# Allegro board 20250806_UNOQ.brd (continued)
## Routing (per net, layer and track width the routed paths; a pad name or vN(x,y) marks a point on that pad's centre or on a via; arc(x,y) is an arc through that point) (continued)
MCU_TRACE_D0: length 69.3
  S6 w0.064: v4(14,4.59) 13.26,4.59 12.41,5.44 9.47,5.44 9.2,5.71 6.23,5.71 4.96,6.98 4.96,14.77 4.22,15.51 4.22,20.24 v4(4.67,20.7)
  G7 w0.064: v4(14,4.59) 14.16,4.75 18.8,4.75 20.13,6.08 20.13,9.33 v5(20.37,9.57) ; v4(4.67,20.7) 5.08,20.7 5.21,20.57 6.5,20.57 7.06,20.02 8,20.02 8.26,20.27 9.96,20.27 10.59,20.9 12.47,20.9 13.15,21.58 v5(13.15,21.86)
  BOTTOM w0.051: MCU1.D3 13.16,22.37 13.16,21.86
  BOTTOM w0.066: JMISC1.6 42.54,10.42 41.58,9.46 20.48,9.46 v5(20.37,9.57) ; 13.16,21.86 v5(13.15,21.86)
MCU_TRACE_D2: length 42.4
  S6 w0.064: v4(12.7,22.38) 12.7,17.47 11.71,16.48 11.71,15.32 17.57,9.46 v5(17.57,9.31)
  G7 w0.064: v4(12.7,22.38) 13.13,22.38 13.31,22.2 v5(13.39,22.2)
  BOTTOM w0.066: v5(17.57,9.31) 17.76,9.5 19.97,9.5 20.29,9.82 21.85,9.82 21.99,9.68 40.28,9.68 41.27,10.67 JMISC1.8
MCU_TRACE_D3: length 66.5
  S6 w0.064: v4(4.88,21.64) 4.95,21.56 4.95,20.5 4.37,19.91 4.37,15.58 5.1,14.85 5.1,7.04 6.29,5.85 9.26,5.85 9.49,5.62 12.45,5.62 13.23,4.84 v4(13.87,4.84)
  G7 w0.064: v4(13.87,4.84) 14,4.97 18.51,4.97 19.56,6.02 19.56,7.96 19.92,8.32 19.92,9.85 v5(19.98,9.91) ; v5(12.9,23.11) 12.69,23.32 12.35,23.32 12.14,23.11 12.14,22.02 11.66,21.54 11.02,21.54 10.9,21.41 8.56,21.41 8.1,20.95 5.36,20.95 4.88,21.44 v4(4.88,21.64)
  BOTTOM w0.066: 40,11.98 40,11.29 38.69,9.98 20.05,9.98 v5(19.98,9.91)
MCU_USART1_RX: length 14.2
  S6 w0.064: v4(4.34,20.7) 4.62,20.98 4.62,23.24 4.57,23.29 v4(4.57,23.34)
  G7 w0.064: v4(4.57,23.34) 4.72,23.5 7.68,23.5 7.94,23.75 9.5,23.75 9.83,24.08 10.82,24.08 11.13,23.77 12.24,23.77 v5(12.4,23.61) ; v5(7.01,19.74) 6.99,19.74 6.3,20.42 4.62,20.42 v4(4.34,20.7)
MCU_USART1_RX_CONN: length 66.5
  S3 w0.064: v3(16.84,1.4) 16.84,1.3 17.22,0.92 21.24,0.92 24.02,3.7 24.02,5.76 24.46,6.2 31.27,6.2 32.56,4.9 48.15,4.9 49.6,6.35 50.6,6.35 50.8,6.15 JDIGITAL1.1
  S6 w0.064: v3(16.84,1.4) 17.3,1.85 17.3,2.79 11.44,8.65 8.9,8.65 6.76,10.79 6.76,12.88 6.92,13.05 6.92,17.38 8.64,19.09 v4(8.64,19.46)
  G7 w0.064: v4(8.64,19.46) 7.62,19.46 v5(7.39,19.23)
  BOTTOM w0.064: R2624.2 v5(7.39,19.23)
MCU_USART1_TX: length 3.5
  BOTTOM w0.051: 15.44,23.37 14.64,23.37 MCU1.B5
  BOTTOM w0.064: 15.44,23.37 15.8,23.01 15.8,22.81 16.13,22.48 R2623.1
MCU_USART1_TX_CONN: length 62.7
  S3 w0.064: JDIGITAL1.2 49.78,6.6 49.55,6.6 48.03,5.08 32.64,5.08 31.34,6.38 24.39,6.38 23.84,5.83 23.84,3.78 21.16,1.1 17.86,1.1 17.64,1.32 v3(17.37,1.32)
  S6 w0.064: v3(17.37,1.32) 18.01,1.32 18.54,1.85 18.54,5.43 18.29,5.68 18.29,6.9 19.14,7.75 v4(19.14,8.92)
  G7 w0.064: v4(19.14,8.92) 19.14,10.51 18.83,10.82 18.83,12.78 18.49,13.12 18.49,13.79 19.53,14.83 v5(19.53,15.16)
  BOTTOM w0.064: R2623.2 18.31,22.48 19.3,21.49 19.3,15.49 19.53,15.27 v5(19.53,15.16)
MCU_VCAP: length 37
  V5 w0.203: v3(7.35,26.69) 8.2,25.84 8.2,19.56 7.39,18.75 v3(7.09,18.75)
  S6 w0.203: v3(7.35,26.69) 7.37,26.69 7.37,26.7 7.39,26.72 v5(7.62,26.72)
  S6 w0.254: v3(7.09,18.75) 7.1,18.76 v4(7.37,18.76)
  G7 w0.203: v5(19.25,14.99) 19.25,15.01 18.87,15.39 8.1,15.39 7.37,16.12 v4(7.37,18.76)
  BOTTOM w0.051: 8.11,26.61 MCU1.N11
  BOTTOM w0.2: MCU1.A4 15.11,23.11 16.15,22.07 C2501.1 16.31,21.84 16.51,21.64 18.14,21.64 18.92,20.85 18.92,15.37 19.23,15.07 19.23,14.99 v5(19.25,14.99)
  BOTTOM w0.203: v5(7.62,26.72) 8,26.72 8.11,26.61
MCU_VREF+: length 91.1
  V5 w0.524: v3(11.74,51.6) 10.71,52.63 7.93,52.63 7.11,51.81 7.11,50.61 4.8,48.3 4.8,32.79 7.7,29.89 7.7,27.96 6.46,26.72 6.44,26.72 5.58,25.86 5.58,22.23 7.14,20.68 v3(7.57,20.68)
  S6 w0.203: v4(7.87,20.68) v3(7.57,20.68)
  S6 w0.254: v3(11.74,51.6) v5(12.04,51.6)
  G7 w0.203: v4(7.87,20.68) 7.95,20.6 v5(8.48,20.6)
  BOTTOM w0.2: v5(8.48,20.6) C2521.1 C2520.1 9.04,20.76 MCU1.L1
  BOTTOM w0.254: v5(12.04,51.6) 12.4,51.24 14.39,51.24 18.5,47.13 18.5,43.3 20.22,41.58 34.14,41.58 34.98,42.42 40.57,42.42 41.26,43.11 U2501.3 44.06,43.63 44.39,43.96 C2614.1 46.6,44.37 48.11,44.37 48.44,44.7 JDIGITAL1.16
MCU_VREF_EN: length 133.3
  TOP w0.066: v2(0.93,19.9) 1.04,19.79 1.04,4.45 1.78,3.71 3.62,3.71 v6(4.16,4.25)
  S3 w0.064: v2(0.93,19.9) v3(1.93,19.9)
  S6 w0.064: v4(3.4,19.65) 3.15,19.9 v3(1.93,19.9)
  G7 w0.064: v5(48.98,3.82) 47.45,5.35 42.13,5.35 40.39,7.09 24.06,7.09 22.89,5.92 22.89,3.51 21.05,1.67 12.71,1.67 8.96,5.42 5.61,5.42 4.45,4.25 v6(4.16,4.25) ; v4(3.4,19.65) 3.61,19.86 5.9,19.86 v5(6.11,19.65)
  BOTTOM w0.058: 9.03,21.87 8.64,21.87 8.42,21.65 8.42,21.33 8.04,20.95 6.51,20.95 5.87,20.31 5.87,19.89 v5(6.11,19.65)
  BOTTOM w0.066: U2501.6 45.37,44.92 R2515.1 47.56,44.92 48.53,45.89 51.64,45.89 52.02,45.51 52.02,4.45 51.39,3.82 v5(48.98,3.82) ; 9.03,21.87 9.27,22.11 MCU1.M2
MIC2_BIAS: length 47.5
  S3 w0.127: v2(43.85,17.59) 43.6,17.35 42.5,17.35 42.41,17.44 40.71,17.44 v2(40.39,17.11)
  S3 w0.15: v2(43.85,17.59) 44.08,17.83 47.01,17.83 48.13,16.71 48.13,9.98 47.39,9.24 47.38,9.24 47.22,9.08 47.22,9.07 45.85,7.7 23.7,7.7 22.49,6.49 22.49,4.26 22.27,4.03 20.89,4.03 20.66,4.26 v3(20.66,4.35)
  S6 w0.15: v3(20.66,4.35) 20.62,4.31 v5(19.94,4.31)
MIC2_BIAS_CONN: length 6.5
  BOTTOM w0.15: JMISC1.33 24.76,7.55 23.19,5.98 22.14,5.98 21.6,5.44 21.04,5.44 20.61,5.01 D26067.2 20.61,4.88 20.61,4.48 R2646.1
MIC2_INN: length 46.1
  S3 w0.127: v2(43.82,17.06) 43.6,16.84 42.7,16.84 42.62,16.76 42.21,16.76 41.72,17.26 41.1,17.26 v2(39.82,15.98)
  S3 w0.15: v2(43.82,17.06) 44.13,17.37 46.83,17.37 47.83,16.37 47.83,10.24 45.62,8.03 23.67,8.03 22.24,6.59 22.24,4.49 22.07,4.32 21.44,4.32 v3(21.35,4.41)
  S6 w0.15: v5(21.02,4.37) 21.31,4.37 v3(21.35,4.41)
MIC2_INN_CONN: length 6.7
  BOTTOM w0.15: R2637.1 21.5,4.39 D26066.2 22.31,5.72 23.3,5.72 24.62,7.04 25.56,7.04 26.05,7.53 26.05,8.07 JMISC1.31
MIC2_INP: length 44.9
  S3 w0.127: v2(39.54,15.7) 40.16,15.7 40.46,16 40.92,16 41.25,16.33 42.48,16.33 42.58,16.23 43.52,16.23 v2(43.82,16.53)
  S3 w0.15: v3(21.87,4.66) 21.95,4.74 21.95,6.64 23.67,8.36 45.42,8.36 47.57,10.52 47.57,16.27 46.76,17.08 44.37,17.08 v2(43.82,16.53)
  S6 w0.15: v5(22.58,4.37) 22.16,4.37 v3(21.87,4.66)
MIC2_INP_CONN: length 7.5
  BOTTOM w0.15: JMISC1.29 27.32,8.07 27.32,7.64 26.41,6.73 24.71,6.73 23.42,5.44 22.39,5.44 22.09,5.14 D26065.2 22.09,4.38 R2636.1
MIPI_DSI0_CLK_M: length 68.9
  TOP w0.058: v2(38.73,50.37) 38.54,50.57 38.3,50.57 38.06,50.81 38.06,51 37.76,51.3 37.53,51.3 U3001.H8
  S3 w0.051: v2(30.17,29.68) 29.97,29.49 29.97,28.85 29.59,28.48 29.59,28.35 29.6,28.35 29.6,28.33
  S3 w0.053: 29.6,28.33 29.6,28.14 27.01,25.55 23.25,25.55 21.79,24.09 19.29,24.09 19.16,24.22 18.94,24.22 v3(18.77,24.05) ; v2(38.73,50.37) 38.93,50.56 39.05,50.56 39.25,50.36 39.25,48.85 39.38,48.72 39.38,48.29 v3(39.2,48.11)
  S6 w0.053: v3(18.77,24.05) 18.58,24.24 18.32,24.24 18.14,24.42 18.14,28.1 18.26,28.22 18.57,28.22 18.62,28.27 18.62,28.47 18.57,28.53 18.26,28.53 18.14,28.65 18.14,28.95 18.26,29.07 18.57,29.07 18.62,29.12 18.62,29.32 18.57,29.38 18.26,29.38 18.14,29.5 18.14,29.8 18.26,29.92 19.1,29.92 19.15,29.97 19.15,30.17 19.1,30.22 18.26,30.22 18.14,30.35 18.14,30.64 18.26,30.76 19.1,30.76 19.15,30.82 19.15,31.02 19.1,31.07 18.26,31.07 18.14,31.19 18.14,31.56 18.26,31.68 19.11,31.68 19.16,31.73 19.16,31.93 19.11,31.99 18.26,31.99 18.14,32.11 18.14,40.1 19.5,41.47 33.17,41.47 34.34,42.64 36.27,42.64 39.38,45.74 39.38,47.93 v3(39.2,48.11)
MIPI_DSI0_CLK_M_CONN: length 22
  TOP w0.058: v2(42.22,51.59) 42.13,51.5 42.13,51.13 41.98,50.98 41.45,50.98 41.32,51.12 41.32,51.53 41.26,51.59 41.14,51.59 41.08,51.53 41.08,51.12 40.94,50.98 40.61,50.98 40.2,50.57 39.44,50.57 39.24,50.37
  S3 w0.053: v3(42.99,53.57) 43.18,53.76 43.18,54.04 43.38,54.24 44.18,54.24 44.5,53.92 44.5,52.61 44.18,52.29 43.53,52.29 43.48,52.24 43.48,52.05 43.36,51.93 43.15,51.93 43.03,52.05 43.03,52.24 42.98,52.29 42.29,52.29 42.11,52.11 42.11,51.7 v2(42.22,51.59)
  S6 w0.053: v3(42.99,53.57) 43.04,53.52 v5(43.04,53.29)
  BOTTOM w0.058: v5(43.04,53.29) 43.14,53.19 43.14,52.91 43.08,52.85 43.07,52.85 43.01,52.79 43.01,52.67 43.07,52.61 43.08,52.61 43.14,52.56 43.14,52.3 43.3,52.15 44.04,52.15 44.16,52.03 44.16,51.59 43.96,51.39 42.18,51.39 42.12,51.45 42.12,51.73 42.3,51.91 U2612.1 U2612.10 42.3,53.24 42.12,53.42 42.12,53.57 42.32,53.77 43.02,53.77 43.25,54 43.25,54.89 43.31,54.95 JMEDIA1.3
MIPI_DSI0_CLK_P: length 68.9
  TOP w0.058: v2(38.73,50.91) 38.54,50.71 38.35,50.71 38.19,50.87 38.19,51.06 37.82,51.43 37.49,51.43 U3001.G8
  S3 w0.051: v2(29.77,29.28) 29.79,29.28 29.86,29.21 29.86,28.9 29.48,28.52 29.48,28.35 29.48,28.35 29.48,28.33
  S3 w0.053: 29.48,28.33 29.48,28.18 26.96,25.67 23.2,25.67 21.74,24.21 20.87,24.21 20.81,24.26 20.81,24.32 20.76,24.37 20.65,24.37 20.6,24.32 20.6,24.26 20.55,24.21 20.44,24.21 20.39,24.26 20.39,24.32 20.33,24.37 20.23,24.37 20.18,24.32 20.18,24.26 20.12,24.21 20.02,24.21 19.96,24.26 19.96,24.32 19.91,24.37 19.8,24.37 19.75,24.32 19.75,24.26 19.7,24.21 19.34,24.21 19.21,24.34 18.96,24.34 v3(18.77,24.53) ; v2(38.73,50.91) 38.73,50.9 38.95,50.68 39.1,50.68 39.37,50.41 39.37,48.9 39.5,48.77 39.5,48.29 v3(39.68,48.11)
  S6 w0.053: v3(39.68,48.11) 39.5,47.93 39.5,45.69 36.32,42.52 34.39,42.52 33.22,41.35 19.55,41.35 18.25,40.05 18.25,32.16 18.31,32.1 19.16,32.1 19.28,31.98 19.28,31.68 19.16,31.56 18.31,31.56 18.25,31.51 18.25,31.24 18.31,31.19 19.15,31.19 19.27,31.07 19.27,30.77 19.15,30.65 18.31,30.65 18.25,30.59 18.25,30.39 18.31,30.34 19.15,30.34 19.27,30.22 19.27,29.92 19.15,29.8 18.31,29.8 18.25,29.75 18.25,29.55 18.31,29.49 18.62,29.49 18.74,29.37 18.74,29.07 18.62,28.95 18.31,28.95 18.25,28.9 18.25,28.7 18.31,28.64 18.62,28.64 18.74,28.52 18.74,28.23 18.62,28.1 18.31,28.1 18.25,28.05 18.25,24.47 18.37,24.36 18.6,24.36 v3(18.77,24.53)
MIPI_DSI0_CLK_P_CONN: length 22
  TOP w0.058: 39.24,50.91 39.24,50.83 39.36,50.71 39.57,50.71 39.63,50.77 39.63,50.82 39.69,50.88 39.8,50.88 39.86,50.82 39.86,50.77 39.92,50.71 40.15,50.71 40.55,51.11 40.89,51.11 40.95,51.17 40.95,51.58 41.08,51.72 41.31,51.72 41.45,51.58 41.45,51.17 41.51,51.11 41.92,51.11 42,51.19 42,51.48 v2(41.89,51.59)
  S3 w0.053: v2(41.89,51.59) 42,51.7 42,52.16 42.25,52.41 43.03,52.41 43.15,52.29 43.15,52.1 43.2,52.05 43.31,52.05 43.36,52.1 43.36,52.29 43.48,52.41 44.13,52.41 44.38,52.66 44.38,53.87 44.13,54.12 43.43,54.12 43.3,53.99 43.3,53.74 v3(43.47,53.57)
  S6 w0.053: v3(43.47,53.57) 43.37,53.47 v5(43.37,53.29)
  BOTTOM w0.058: v5(43.37,53.29) 43.27,53.19 43.27,52.36 43.35,52.28 44.1,52.28 44.29,52.09 44.29,51.53 44.02,51.26 42.12,51.26 41.98,51.39 41.98,51.73 41.8,51.91 U2612.2 U2612.9 41.8,53.23 41.99,53.42 41.99,53.63 42.26,53.9 42.96,53.9 43.11,54.05 43.11,54.89 43.05,54.95 JMEDIA1.5
MIPI_DSI0_L0_M: length 68.9
  TOP w0.058: v2(38.71,51.69) 38.49,51.91 38.07,51.91 37.9,52.08 37.51,52.08 U3001.F8 ; 30.17,28.48 v2(30.12,28.35)
  S3 w0.053: v2(30.12,28.35) 30.04,28.35 30.02,28.33 30.02,28.03 27.24,25.25 23.5,25.25 21.39,23.14 19.53,23.14 v3(19.33,22.94) ; v2(38.71,51.69) 38.9,51.88 39.15,51.88 40.12,50.91 40.12,49.86 v3(39.94,49.68)
  S6 w0.053: v3(39.94,49.68) 40.12,49.5 40.12,49.25 40.66,48.71 40.66,47.06 40.59,46.98 40.33,46.98 40.28,47.04 40.28,48.32 39.89,48.71 38.94,48.71 38.69,48.46 38.69,45.74 36.1,43.14 34.19,43.14 32.95,41.9 19.26,41.9 17.63,40.27 17.63,24.32 18.84,23.11 19.15,23.11 v3(19.33,22.94)
MIPI_DSI0_L0_M_CONN: length 22
  TOP w0.058: R1503.2 39.42,51.89 39.75,51.89 39.99,51.65 40.23,51.65 40.34,51.54 v2(40.35,51.54)
  S3 w0.053: v2(40.35,51.54) 40.47,51.66 40.89,51.66 41.41,51.14 41.41,50.58 41.32,50.49 41.11,50.49 v3(40.92,50.68)
  S6 w0.053: v3(40.92,50.68) 40.85,50.61 v5(40.65,50.61) ; v5(42.3,50.7) 42.49,50.51 42.86,50.51 43.19,50.84 43.19,51.34 43.14,51.39 43.05,51.39 42.99,51.44 42.99,51.55 43.05,51.6 43.14,51.6 43.19,51.66 43.19,51.76 43.14,51.82 43.05,51.82 42.99,51.87 42.99,51.98 43.05,52.03 43.14,52.03 43.19,52.08 43.19,52.39 44.24,53.44 44.24,55.53 44.11,55.66 43.69,55.66 43.64,55.61 43.64,55.4 43.52,55.28 43.32,55.28 43.19,55.4 43.19,55.61 43.14,55.66 43.03,55.66 42.98,55.61 42.98,55.4 42.86,55.28 42.66,55.28 42.53,55.4 42.53,55.61 42.48,55.66 41.76,55.66 41.6,55.82 41.6,56.07 v5(41.48,56.19)
  BOTTOM w0.058: v5(41.48,56.19) 41.59,56.29 41.59,56.77 41.19,57.17 39.79,57.17 39.3,57.66 39.3,58.79 39.24,58.85 JMEDIA1.12 ; v5(42.3,50.7) U2611.10 41.16,50.7 40.98,50.52 40.74,50.52 v5(40.65,50.61)
MIPI_DSI0_L0_P: length 68.8
  TOP w0.058: SOC1.R30 v2(29.82,28.35) ; v2(38.71,52.22) 38.53,52.04 38.13,52.04 37.96,52.21 37.51,52.21 U3001.E8
  S3 w0.053: v2(29.82,28.35) 29.89,28.35 29.91,28.33 29.91,28.08 27.2,25.37 23.45,25.37 21.34,23.26 20.08,23.26 20.03,23.31 20.03,23.37 19.97,23.42 19.87,23.42 19.81,23.37 19.81,23.31 19.76,23.26 19.49,23.26 v3(19.33,23.41) ; v3(40.41,49.68) 40.23,49.86 40.23,50.95 39.19,51.99 38.94,51.99 v2(38.71,52.22)
  S6 w0.053: v3(40.41,49.68) 40.23,49.5 40.23,49.3 40.78,48.76 40.78,47.01 40.64,46.87 40.28,46.87 40.16,46.99 40.16,48.27 39.84,48.59 38.99,48.59 38.81,48.41 38.81,45.69 36.14,43.03 34.24,43.03 32.99,41.78 19.3,41.78 17.74,40.22 17.74,24.37 18.88,23.23 19.15,23.23 v3(19.33,23.41)
MIPI_DSI0_L0_P_CONN: length 22
  TOP w0.058: v2(40.35,51.87) 40.26,51.78 40.05,51.78 39.81,52.02 39.42,52.02 R1504.2
  S3 w0.053: v2(40.35,51.87) 40.44,51.78 40.94,51.78 41.53,51.19 41.53,50.53 41.37,50.37 41.09,50.37 v3(40.92,50.2)
  S6 w0.053: v3(40.92,50.2) 40.84,50.28 v5(40.65,50.28) ; v5(42.3,50.2) 42.49,50.39 42.91,50.39 43.31,50.79 43.31,52.34 44.36,53.39 44.36,55.58 44.16,55.78 43.65,55.78 43.52,55.66 43.52,55.45 43.47,55.4 43.36,55.4 43.31,55.45 43.31,55.66 43.19,55.78 42.99,55.78 42.86,55.66 42.86,55.45 42.81,55.4 42.7,55.4 42.65,55.45 42.65,55.66 42.53,55.78 41.81,55.78 41.72,55.87 41.72,56.09 v5(41.81,56.19)
  BOTTOM w0.058: v5(40.65,50.28) 40.75,50.38 40.98,50.38 41.16,50.2 U2611.9 v5(42.3,50.2) ; JMEDIA1.10 39.5,58.85 39.44,58.79 39.44,57.71 39.85,57.3 41.25,57.3 41.72,56.83 41.72,56.27 v5(41.81,56.19)
MIPI_DSI0_L1_M: length 68.8
  TOP w0.058: U3001.H6 36.71,51.01 36.71,50.63 37.1,50.24 37.1,49.88 v2(36.91,49.68)
  S3 w0.05: v2(31.04,28.47) 31.16,28.35 31.16,28.33
  S3 w0.053: 31.16,28.33 31.16,27.8 27.77,24.42 24.47,24.42 20.75,20.7 20.68,20.7 20.67,20.71 20.59,20.71 20.52,20.64 20.52,20.56 20.53,20.55 20.53,20.47 20.45,20.4 20.37,20.4 20.36,20.41 20.29,20.41 20.21,20.33 20.21,20.26 20.22,20.25 20.22,20.17 20.09,20.04 19.74,20.04 19.69,20.09 19.69,20.15 19.63,20.2 19.53,20.2 19.47,20.15 19.47,20.09 19.42,20.04 19.2,20.04 v3(19.02,20.21) ; v2(36.91,49.68) 36.91,49.46 v3(36.96,49.4)
  S6 w0.053: v3(36.96,49.4) 37.12,49.56 37.12,49.79 37.26,49.93 37.83,49.93 38.07,49.69 38.07,49.06 37.03,48.02 37.03,45.26 35.76,43.99 33.98,43.99 32.55,42.56 18.98,42.56 16.86,40.43 16.86,24.21 18.47,22.6 18.47,20.2 18.65,20.02 18.83,20.02 v3(19.02,20.21)
MIPI_DSI0_L1_M_CONN: length 22.3
  TOP w0.058: v2(40.12,48.52) 40.23,48.62 40.23,48.82 40.09,48.96 39.48,48.96 38.8,48.28 37.32,48.28 37.11,48.49 37.11,48.98 R1505.2
  S3 w0.053: v2(40.12,48.52) 40.23,48.63 40.23,48.83 40.41,49.01 41.19,49.01 v3(41.36,49.18)
  S6 w0.053: v3(41.36,49.18) 41.62,49.18 v5(41.64,49.2)
  BOTTOM w0.058: JMEDIA1.6 43.05,58.85 43.11,58.79 43.11,57.85 43.37,57.59 44.99,57.59 46.24,56.34 46.24,53.26 44.86,51.88 44.86,50.75 43.13,49.02 42.71,49.02 42.53,49.2 U2611.4 v5(41.64,49.2) U2611.7
MIPI_DSI0_L1_P: length 68.8
  TOP w0.058: v2(37.44,49.68) 37.24,49.89 37.24,50.29 36.84,50.69 36.84,51.01 U3001.H7
  S3 w0.05: 31.27,28.33 31.27,28.35 31.27,28.35 31.27,28.64 31.16,28.74 31.16,28.75 v2(31.04,28.87)
  S3 w0.053: v3(37.44,49.4) v2(37.44,49.68) ; 31.27,28.33 31.27,27.75 27.82,24.3 24.52,24.3 20.14,19.92 19.21,19.92 v3(19.02,19.74)
  S6 w0.053: v3(37.44,49.4) 37.23,49.61 37.23,49.74 37.31,49.81 37.78,49.81 37.96,49.64 37.96,49.11 36.92,48.07 36.92,45.31 35.71,44.11 33.93,44.11 32.5,42.67 18.93,42.67 16.74,40.48 16.74,24.16 18.35,22.55 18.35,20.15 18.6,19.9 18.81,19.9 18.97,19.74 v3(19.02,19.74)
MIPI_DSI0_L1_P_CONN: length 22.3
  TOP w0.058: v2(40.45,48.52) 40.36,48.61 40.36,48.88 40.15,49.09 39.42,49.09 38.74,48.41 37.38,48.41 37.24,48.55 37.24,48.98 R1506.2
  S3 w0.053: v3(41.36,48.7) 41.17,48.89 40.46,48.89 40.34,48.78 40.34,48.63 v2(40.45,48.52)
  S6 w0.053: v3(41.36,48.7) v5(41.64,48.7)
  BOTTOM w0.058: JMEDIA1.4 43.31,58.85 43.25,58.79 43.25,57.9 43.43,57.72 45.05,57.72 46.37,56.4 46.37,53.2 44.99,51.82 44.99,50.69 43.18,48.88 42.72,48.88 42.54,48.7 U2611.5 v5(41.64,48.7) U2611.6
MIPI_DSI0_L2_M: length 68.9
  TOP w0.058: v2(38.71,52.93) 38.51,53.13 38.33,53.13 38.07,52.88 37.51,52.88 U3001.D8
  S3 w0.053: v3(39.01,52.96) 38.74,52.96 v2(38.71,52.93) ; v3(19.22,21.66) 19.41,21.84 20.4,21.84 20.93,22.37 21.2,22.37 23.78,24.95 27.48,24.95 30.43,27.9 30.43,28.74 v2(30.57,28.88)
  S6 w0.053: v3(19.22,21.66) 18.98,21.9 18.8,21.9 18.68,22.03 18.68,22.79 17.18,24.29 17.18,40.4 19.09,42.31 32.65,42.31 33.98,43.64 36,43.64 38.21,45.84 38.21,48.59 38.5,48.88 38.5,50.28 39.22,51 39.4,51 39.52,50.87 39.6,50.87 39.67,50.95 39.67,51.02 39.55,51.15 39.55,51.32 39.8,51.58 39.8,52.9 39.55,53.15 39.2,53.15 v3(39.01,52.96)
MIPI_DSI0_L2_M_CONN: length 22.3
  TOP w0.058: R1507.2 39.4,53.12 39.5,53.12 v2(39.6,53.02)
  S3 w0.053: v3(41.41,54.63) 41.24,54.8 40.99,54.8 40.74,55.05 40.74,56.85 40.63,56.96 40.26,56.96 40.14,56.84 40.14,56.11 40.02,55.99 39.01,55.99 38.96,55.94 38.96,55.83 39.01,55.78 40.02,55.78 40.14,55.65 40.14,55.45 40.02,55.33 39.01,55.33 38.96,55.28 38.96,55.17 39.01,55.12 40.02,55.12 40.14,54.99 40.14,53.86 40.19,53.81 40.24,53.81 40.29,53.76 40.29,53.65 40.24,53.6 40.19,53.6 40.14,53.55 40.14,53.27 40,53.13 39.71,53.13 v2(39.6,53.02)
  S6 w0.053: v5(40.71,52.05) 40.6,52.16 40.6,52.39 40.53,52.46 40.53,53.35 40.58,53.4 41.29,53.4 41.41,53.52 41.41,53.72 41.29,53.85 40.58,53.85 40.53,53.9 40.53,54.68 40.66,54.81 41.23,54.81 v3(41.41,54.63)
  BOTTOM w0.058: JMEDIA1.9 39.5,54.95 39.44,54.89 39.44,54.04 39.68,53.8 40.42,53.8 40.62,53.6 40.62,53.2 U2612.7 U2612.4 v5(40.71,52.05)
MIPI_DSI0_L2_P: length 68.9
  TOP w0.058: U3001.C8 37.51,53.01 38.02,53.01 38.27,53.26 38.53,53.26 v2(38.71,53.44)
  S3 w0.053: v3(19.22,22.14) 19.4,21.96 19.7,21.96 19.76,22.01 19.76,22.11 19.81,22.16 19.92,22.16 19.97,22.11 19.97,22.01 20.02,21.96 20.35,21.96 20.88,22.49 21.16,22.49 23.73,25.07 27.43,25.07 30.31,27.95 30.31,28.74 v2(30.17,28.88) ; v3(39.01,53.44) v2(38.71,53.44)
  S6 w0.053: v3(39.01,53.44) 39.19,53.26 39.6,53.26 39.92,52.95 39.92,51.53 39.66,51.27 39.66,51.2 39.79,51.07 39.79,50.9 39.65,50.76 39.47,50.76 39.35,50.88 39.27,50.88 38.62,50.23 38.62,48.83 38.33,48.54 38.33,45.8 36.05,43.52 34.03,43.52 32.7,42.19 19.13,42.19 17.3,40.35 17.3,24.34 18.8,22.84 18.8,22.07 18.85,22.02 19.11,22.02 v3(19.22,22.14)
MIPI_DSI0_L2_P_CONN: length 22.3
  TOP w0.058: v2(39.6,53.35) 39.5,53.25 39.4,53.25 R1508.2
  S3 w0.053: v3(41.41,55.11) 41.22,54.92 41.04,54.92 40.86,55.1 40.86,56.9 40.68,57.08 40.21,57.08 40.02,56.89 40.02,56.16 39.97,56.11 38.96,56.11 38.84,55.98 38.84,55.78 38.96,55.66 39.97,55.66 40.02,55.61 40.02,55.5 39.97,55.45 38.96,55.45 38.84,55.32 38.84,55.12 38.96,55 39.97,55 40.02,54.95 40.02,53.32 39.95,53.24 39.71,53.24 v2(39.6,53.35)
  S6 w0.053: v5(40.38,52.05) 40.48,52.15 40.48,52.34 40.41,52.41 40.41,53.39 40.53,53.52 41.24,53.52 41.3,53.57 41.3,53.68 41.24,53.73 40.53,53.73 40.41,53.85 40.41,54.73 40.61,54.93 41.23,54.93 v3(41.41,55.11)
  BOTTOM w0.058: JMEDIA1.11 39.24,54.95 39.3,54.89 39.3,53.99 39.62,53.67 40.36,53.67 40.49,53.54 40.49,53.2 U2612.6 U2612.5 40.3,52.13 v5(40.38,52.05)
MIPI_DSI0_L3_M: length 68.9
  TOP w0.058: v2(35.71,49.68) 35.91,49.88 35.91,51.01 U3001.H4
  S3 w0.05: 30.65,28.4 30.64,28.39 30.64,28.33 ; v2(30.57,29.28) 30.64,29.21
  S3 w0.053: 30.64,28.33 30.64,27.76 27.65,24.77 24.03,24.77 21.03,21.77 20.96,21.77 20.94,21.79 20.86,21.79 20.78,21.71 20.78,21.64 20.81,21.62 20.81,21.54 20.73,21.47 20.66,21.47 20.63,21.49 20.56,21.49 20.48,21.41 20.48,21.34 20.5,21.32 20.5,21.24 20.37,21.11 20.15,21.11 20.1,21.16 20.1,21.21 20.04,21.26 19.94,21.26 19.88,21.21 19.88,21.16 19.83,21.11 19.72,21.11 19.67,21.16 19.67,21.21 19.62,21.26 19.51,21.26 19.46,21.21 19.46,21.16 19.4,21.11 19.3,21.11 19.24,21.16 19.24,21.21 19.19,21.26 19.08,21.26 19.03,21.21 19.03,21.16 18.98,21.11 18.87,21.11 18.82,21.16 18.82,21.21 18.76,21.26 18.66,21.26 18.6,21.21 18.6,21.16 18.55,21.11 18.44,21.11 18.39,21.16 18.39,21.21 18.34,21.26 18.23,21.26 18.18,21.21 18.18,21.16 18.12,21.11 17.93,21.11 17.83,21.21 v3(17.83,21.44) ; 30.65,28.4 30.65,28.71 30.74,28.81 30.74,28.96 30.64,29.06 30.64,29.21 ; v2(35.71,49.68) 35.71,49.43 v3(35.74,49.4)
  S6 w0.053: v3(17.83,21.44) 17.58,21.44 17.42,21.59 17.42,22.82 16.45,23.8 16.45,40.6 18.81,42.96 32.38,42.96 33.94,44.53 35.59,44.53 36.63,45.57 36.63,47.78 36.18,48.23 36,48.23 35.87,48.1 35.8,48.1 35.72,48.17 35.72,48.25 35.85,48.38 35.85,48.55 35.23,49.18 35.23,49.53 35.42,49.72 35.87,49.72 35.92,49.67 35.92,49.58 v3(35.74,49.4)
MIPI_DSI0_L3_M_CONN: length 22.2
  TOP w0.058: R1509.2 35.9,48.99 35.9,48.71 35.84,48.65 35.66,48.65 35.6,48.59 35.6,48.47 35.66,48.41 35.84,48.41 35.9,48.36 35.9,47.91 35.19,47.2 31.42,47.2 31.33,47.29 31.33,47.61 31.43,47.71 34.4,47.71 34.61,47.92 34.61,48.37 34.41,48.57 33.55,48.57 v2(33.44,48.68)
  S3 w0.053: v2(33.44,48.68) 33.24,48.68 v3(33.15,48.77)
  S6 w0.053: v5(32.87,48.69) 33.07,48.69 v3(33.15,48.77)
  BOTTOM w0.058: v5(32.87,48.69) 32.78,48.6 32.48,48.6 32.41,48.67 32.41,49.57 34.45,51.6 34.45,51.83 34.63,52.01 U2606.1 U2606.10 34.44,53.31 34.44,53.62 34.56,53.74 35.49,53.74 35.63,53.88 35.63,54.89 35.69,54.95 JMEDIA1.15
MIPI_DSI0_L3_P: length 68.9
  TOP w0.058: v2(36.22,49.68) 36.04,49.86 36.04,51.01 U3001.H5
  S3 w0.05: 30.76,29.25 30.76,29.22 30.76,29.22 30.76,29.21 ; 30.76,29.49 v2(30.57,29.68) ; 30.76,28.33 30.76,28.34 30.76,28.35 30.76,28.38 30.76,28.38 30.76,28.4
  S3 w0.053: v3(36.22,49.4) v2(36.22,49.68) ; 30.76,29.21 30.76,29.1 30.86,29 30.86,28.76 30.76,28.66 30.76,28.4 ; 30.76,28.33 30.76,27.71 27.7,24.65 24.08,24.65 20.42,20.99 17.88,20.99 17.77,21.1 v3(17.49,21.1) ; 30.76,29.25 30.76,29.49
  S6 w0.053: v3(17.49,21.1) 17.49,21.36 17.31,21.54 17.31,22.77 16.33,23.75 16.33,40.65 18.77,43.08 32.33,43.08 33.89,44.64 35.54,44.64 36.51,45.62 36.51,47.73 36.13,48.11 36.05,48.11 35.92,47.98 35.75,47.98 35.61,48.12 35.61,48.3 35.74,48.43 35.74,48.5 35.11,49.13 35.11,49.58 35.37,49.84 35.92,49.84 36.04,49.72 36.04,49.58 v3(36.22,49.4)
MIPI_DSI0_L3_P_CONN: length 22.1
  TOP w0.058: v2(33.44,48.35) 33.53,48.44 34.35,48.44 34.48,48.31 34.48,47.98 34.34,47.84 31.37,47.84 31.2,47.67 31.2,47.23 31.36,47.07 35.25,47.07 36.03,47.85 36.03,48.99 R1510.2
  S3 w0.053: v3(33.15,48.29) 33.21,48.35 v2(33.44,48.35)
  S6 w0.053: v5(32.87,48.36) 33.08,48.36 v3(33.15,48.29)
  BOTTOM w0.058: 34.92,54.95 35.43,54.95 35.49,54.89 35.49,53.93 35.43,53.87 34.5,53.87 34.31,53.68 34.31,53.29 U2606.9 U2606.2 34.13,52.01 34.31,51.83 34.31,51.66 32.28,49.62 32.28,48.61 32.42,48.47 32.76,48.47 v5(32.87,48.36)
MUX_ALERT: length 51
  TOP w0.066: SOC1.AG29 24.99,28.88 v2(25.32,28.55) ; U3001.B8 37.54,53.54 v2(37.64,53.44) 38.25,54.05 R3025.2
  S3 w0.064: v3(39.41,43.62) 39.41,46.13 38.5,47.04 38.5,50 38.28,50.22 38.28,51.88 37.64,52.52 v2(37.64,53.44) ; v3(19.53,28.21) 20.17,28.21 20.22,28.26 25.03,28.26 v2(25.32,28.55)
  S6 w0.064: v3(19.53,28.21) 19.53,28.57 19.86,28.91 19.86,36.77 19.5,37.13 19.5,38.17 22.12,40.79 33.19,40.79 34.51,42.11 36.52,42.11 37.34,42.94 38.72,42.94 v3(39.41,43.62)
MUX_CABLE_DET: length 42.3
  TOP w0.066: v2(22.55,49.79) 22.01,49.25 v2(14.89,49.25) ; SOC1.AG1 v2(24.54,40.51) ; TP3007.1 33.43,52.07 v2(33.83,51.66)
  S3 w0.064: v3(22.47,50.22) 22.55,50.14 v2(22.55,49.79) ; v2(14.89,49.25) 14.95,49.25 15.83,48.37 15.83,45.46 18.59,42.7 20.47,42.7 22.56,40.61 24.43,40.61 v2(24.54,40.51) ; v2(35.37,53.14) 35.37,53.1 35.15,52.88 34.52,52.88 34.44,52.81 34.44,52.27 v2(33.83,51.66) 33.71,51.54 33.71,51.05 34.37,50.39 34.37,50.08 34.21,49.92 32.96,49.92 32.17,50.71 30.7,50.71 30.5,50.91 v3(30.09,50.91)
  S6 w0.064: v3(22.47,50.22) 26.26,50.22 26.34,50.3 26.34,50.89 26.52,51.07 29.93,51.07 v3(30.09,50.91)
MUX_DP_HPD: length 4.9
  TOP w0.066: R3028.2 34.99,41.86 32.18,41.86 31.77,41.45 SOC1.K1
MUX_DP_HPD_R: length 15.5
  TOP w0.066: R3028.1 35.77,41.88 39.1,41.88 v2(39.25,41.73)
  S3 w0.064: v2(36.98,52.32) 37.02,52.32 37.82,51.52 37.82,50.01 37.97,49.86 37.97,46.75 38.51,46.21 38.51,42.15 38.71,41.95 39.03,41.95 v2(39.25,41.73)
MUX_I2C_SCL_R: length 14
  TOP w0.066: v2(38.8,43.72) 38.35,43.72 37.97,44.1 36.17,44.1 35.89,43.82 TP3002.1 35.51,43.78 R3014.2
  S3 w0.064: v2(38.8,43.72) 38.8,46.23 38.15,46.88 38.15,49.9 37.97,50.08 37.97,51.63 37.02,52.58 37.02,52.74 v2(36.98,52.78)
MUX_I2C_SDA_R: length 19.2
  TOP w0.066: v2(39.01,43.93) 38.39,43.93 37.53,44.79 31.35,44.79 TP3003.1 30.99,44.43 R3015.2
  S3 w0.064: v2(39.01,43.93) 39.01,44.48 38.98,44.51 38.98,46.3 38.32,46.96 38.32,49.94 38.13,50.13 38.13,51.76 37.2,52.69 37.2,52.92 v2(37.01,53.11)
MUX_LDO_EN: length 1.1
  TOP w0.066: 25.7,60.83 25.7,60.82 U3004.3
MUX_POWER_EN: length 55.1
  TOP w0.066: SOC1.AE1 25.77,40.45 25.58,40.64 v2(25.5,40.64)
  G2 w0.191: v2(34.77,52.58) 34.8,52.58 v1(34.95,52.73)
  S3 w0.064: v3(35.05,52.53) 34.98,52.53 34.92,52.58 v2(34.77,52.58) ; v3(15.03,51.54) 14.37,50.88 14.37,50.16 16.03,48.5 16.03,45.49 18.64,42.88 20.56,42.88 22.68,40.76 25.39,40.76 v2(25.5,40.64)
  S6 w0.064: v3(15.03,51.54) 15.15,51.42 v5(15.3,51.42) ; v5(35.26,52.73) v3(35.05,52.53)
  BOTTOM w0.066: v5(35.26,52.73) 35.43,52.91 C3028.1 35.59,52.68 R3022.2 35.59,52.13 33.44,49.98 33.44,48.15 32.76,47.47 32.76,44.82 30.3,42.36 20.43,42.36 19.37,43.43 19.37,47.36 15.99,50.74 ; TP3001.1 16.01,50.74 15.99,50.74 ; 15.99,50.74 v5(15.3,51.42)
MUX_RESET_N: length 43.1
  TOP w0.066: C3027.1 38.68,55.32 TP3006.1 38.53,54.79 R3023.2 v2(38.71,54.43)
  S3 w0.064: v3(19.24,38.33) 19.77,38.33 19.92,38.48 v2(25.37,38.48) ; 37.97,53.49 37.8,53.66 37.09,53.66 v2(37.02,53.59) ; 37.97,53.49 37.97,52.49 38.43,52.02 38.43,50.28 38.66,50.06 38.66,47.2 v3(40.08,45.78) ; 37.97,53.49 37.97,53.71 38.08,53.82 38.38,53.82 38.71,54.15 v2(38.71,54.43)
  S6 w0.064: v3(40.08,45.78) 39.99,45.78 36.5,42.29 34.49,42.29 33.22,41.02 22.15,41.02 19.46,38.33 v3(19.24,38.33)
MUX_SBU1: length 4.9
  TOP w0.051: v2(35.73,59.77) U2602.1 35.73,58.61 35.88,58.46 35.88,58.19 C3019.2 34.93,58.01 R3003.2
  S3 w0.048: v2(36.97,61.23) 37.03,61.17 37.03,60.98 36.59,60.53 36.18,60.53 35.9,60.26 35.9,59.94 v2(35.73,59.77)
MUX_SBU2: length 8.2
  TOP w0.051: v2(36.23,59.77) U2602.2 36.23,58.62 36.06,58.45 36.06,58.19 C3020.2 R3004.2
  S3 w0.048: v2(38.72,62.53) 38.33,62.92 37.27,62.92 36.97,62.62 36.97,61.59 37.19,61.37 37.19,60.91 36.66,60.38 36.25,60.38 36.06,60.19 36.06,59.94 v2(36.23,59.77)
MUX_SSRXN1: length 20.1
  TOP w0.053: v2(44.2,58.75) 44.08,58.87 44.08,59.66 43.92,59.82 43.92,60.82 44.21,61.11 R2665.1 C2629.2
  S3 w0.051: v3(44.26,59.03) 44.26,58.81 v2(44.2,58.75) ; v2(35.37,53.54) 35.51,53.68 35.51,53.87 35.13,54.25 35.13,55.38 35.08,55.43 34.97,55.43 34.92,55.48 34.92,55.58 34.97,55.63 35.08,55.63 35.13,55.68 35.13,55.86 v3(34.95,56.03)
  S6 w0.051: v3(34.95,56.03) 35.13,56.21 35.13,56.54 35.41,56.82 37.23,56.82 37.74,56.31 40.03,56.31 41.73,58.02 44.29,58.02 44.7,58.42 44.7,59.41 44.55,59.56 44.22,59.56 44.08,59.42 44.08,59.2 v3(44.26,59.03)
MUX_SSRXN1_C: length 7.4
  TOP w0.053: D26102.2 44.16,62.77 ; 44.16,62.77 43.92,63.01 43.92,63.54 43.52,63.94 42.19,63.94 42.06,64.07 40.35,64.07 39.9,63.62 39.9,63.04 39.72,62.86 JUSB1.B10 ; 44.16,62.77 44.13,62.77 43.92,62.56 43.92,62.47 44.18,62.21 44.25,62.21 C2629.1
MUX_SSRXN2: length 6.6
  TOP w0.053: U3001.A3 35.24,54.07 35.24,54.41 34.63,55.03 34.35,55.03 33.25,56.13 33.25,57.14 R2660.1 33.24,57.57 33.24,58.17 32.94,58.47 32.44,58.47 C2627.1
MUX_SSRXN2_C: length 10.3
  TOP w0.053: JUSB1.A10 35.97,60.86 35.79,60.68 35.79,60.53 35.16,59.9 32.59,59.9 32.34,59.64 31.83,59.64 31.64,59.45 U2601.6 U2601.5 30.27,59.45 30.09,59.63 29.93,59.63 29.87,59.57 29.87,58.73 30.13,58.47 30.76,58.47 30.81,58.52 30.81,58.57 30.87,58.62 30.97,58.62 31.03,58.57 31.03,58.52 31.08,58.47 31.56,58.47 C2627.2
MUX_SSRXP1: length 20.3
  TOP w0.053: C2630.2 R2664.1 43.46,61.11 43.78,60.8 43.78,59.76 43.94,59.6 43.94,58.87 v2(43.82,58.75)
  S3 w0.051: v2(43.82,58.75) 43.76,58.81 43.76,59.01 v3(43.78,59.03) ; v3(35.43,56.03) 35.25,55.85 35.25,54.3 35.63,53.92 35.63,53.69 v2(35.77,53.54)
  S6 w0.051: v3(43.78,59.03) 43.96,59.21 43.96,59.47 44.17,59.68 44.6,59.68 44.82,59.46 44.82,58.37 44.35,57.89 41.78,57.89 40.08,56.19 37.69,56.19 37.18,56.7 35.46,56.7 35.25,56.49 35.25,56.21 v3(35.43,56.03)
MUX_SSRXP1_C: length 7.3
  TOP w0.053: JUSB1.B11 40.22,62.85 40.04,63.03 40.04,63.56 40.41,63.93 40.65,63.93 40.7,63.88 40.7,63.83 40.76,63.78 40.86,63.78 40.92,63.83 40.92,63.88 40.97,63.93 41.08,63.93 41.13,63.88 41.13,63.83 41.18,63.78 41.29,63.78 41.34,63.83 41.34,63.88 41.4,63.93 42.01,63.93 42.13,63.8 43.46,63.8 43.78,63.48 43.78,63.03 43.54,62.79 ; D26103.2 43.54,62.79 ; 43.54,62.79 43.58,62.79 43.78,62.59 43.78,62.48 43.51,62.21 C2630.1
MUX_SSRXP2: length 6.6
  TOP w0.053: C2628.1 32.44,58.34 32.88,58.34 33.1,58.11 33.1,57.59 R2661.1 33.11,57.1 33.11,56.07 34.29,54.89 34.57,54.89 34.75,54.71 34.75,54.63 34.72,54.61 34.72,54.53 34.8,54.46 34.87,54.46 34.9,54.48 34.98,54.48 35.1,54.36 35.1,54.07 U3001.A2
MUX_SSRXP2_C: length 10.4
  TOP w0.053: JUSB1.A11 35.47,60.87 35.65,60.69 35.65,60.59 35.1,60.03 32.53,60.03 32.28,59.78 31.81,59.78 31.64,59.95 U2601.7 U2601.4 30.25,59.95 30.07,59.77 29.87,59.77 29.73,59.63 29.73,58.67 30.07,58.33 31.57,58.33 C2628.2
MUX_SSTXN1: length 11.5
  TOP w0.053: v2(36.21,54.57) 36.3,54.48 36.3,54.07 U3001.A5
  S3 w0.051: v3(43.38,56.6) 43.19,56.79 42.85,56.79 42.67,56.97 42.67,57.48 v2(42.46,57.69) ; v2(36.21,54.57) 36.21,54.8 v3(36.15,54.86)
  S6 w0.051: v3(36.15,54.86) 36.32,54.69 36.32,54.36 36.46,54.23 37.87,54.23 39.3,55.65 40.24,55.65 41.37,56.78 43.2,56.78 v3(43.38,56.6)
MUX_SSTXN1_C: length 6.1
  TOP w0.053: C2602.1 42.64,58.38 42.64,58.95 D26105.2 42.65,59.32 42.65,60.14 42.49,60.3 39.83,60.3 39.65,60.48 39.65,60.68 39.47,60.86 JUSB1.A3
MUX_SSTXN2: length 19.7
  S3 w0.051: v3(38.63,57.94) 38.46,57.77 38.46,54.78 37.62,53.94 36.65,53.94 36.44,53.73 36.44,53.68 v2(36.57,53.54) ; v2(28.65,59.62) 28.87,59.4 28.87,58.85 29.11,58.61 29.11,57.24 v3(28.92,57.05)
  S6 w0.051: v3(28.92,57.05) 29.11,57.23 29.11,57.37 29.33,57.59 32.05,57.59 32.44,57.98 35.84,57.98 36.56,58.7 38.1,58.7 38.45,58.35 38.45,58.12 v3(38.63,57.94)
MUX_SSTXN2_C: length 11.8
  TOP w0.053: JUSB1.B3 36.22,62.89 36.04,63.07 36.04,63.66 35.69,64.01 33.22,64.01 32.2,63 32.2,61.41 32.06,61.27 31.82,61.27 31.64,61.45 U2601.10 U2601.1 30.25,61.45 30.07,61.27 29.22,61.27 28.89,60.94 28.89,60.36 C2603.1
MUX_SSTXP1: length 11.4
  TOP w0.053: v2(36.54,54.57) 36.44,54.48 36.44,54.07 U3001.A6
  S3 w0.051: v3(43.38,57.08) 43.21,56.91 42.9,56.91 42.79,57.02 42.79,57.48 v2(42.99,57.69) ; v2(36.54,54.57) 36.54,54.77 v3(36.63,54.86)
  S6 w0.051: v3(36.63,54.86) 36.45,54.68 36.45,54.41 36.51,54.35 36.76,54.35 36.81,54.4 36.81,54.43 36.87,54.48 36.97,54.48 37.02,54.43 37.02,54.4 37.07,54.35 37.17,54.35 37.22,54.4 37.22,54.43 37.27,54.48 37.37,54.48 37.42,54.43 37.42,54.4 37.48,54.35 37.82,54.35 39.25,55.77 40.19,55.77 41.32,56.9 43.2,56.9 v3(43.38,57.08)
MUX_SSTXP1_C: length 6.1
  TOP w0.053: JUSB1.A2 39.97,60.85 39.79,60.67 39.79,60.53 39.89,60.44 42.55,60.44 42.79,60.2 42.79,59.3 D26104.2 42.78,58.95 42.78,58.41 C2601.1
MUX_SSTXP2: length 19.6
  S3 w0.051: v3(38.15,57.94) 38.33,57.76 38.33,54.83 37.93,54.42 37.85,54.42 37.82,54.45 37.75,54.45 37.68,54.38 37.68,54.3 37.71,54.27 37.71,54.2 37.57,54.07 37.26,54.07 37.21,54.12 37.21,54.15 37.16,54.2 37.06,54.2 37.01,54.15 37.01,54.12 36.96,54.07 36.6,54.07 36.32,53.78 36.32,53.69 v2(36.17,53.54) ; v2(29.2,59.62) 28.99,59.41 28.99,58.9 29.23,58.66 29.23,57.22 v3(29.4,57.05)
  S6 w0.051: v3(38.15,57.94) 38.33,58.11 38.33,58.3 38.05,58.58 36.61,58.58 35.89,57.86 32.49,57.86 32.1,57.47 29.38,57.47 29.23,57.32 29.23,57.22 v3(29.4,57.05)
MUX_SSTXP2_C: length 11.7
  TOP w0.053: JUSB1.B2 35.72,62.9 35.9,63.08 35.9,63.6 35.63,63.87 35.45,63.87 35.4,63.82 35.4,63.77 35.34,63.72 35.24,63.72 35.18,63.77 35.18,63.82 35.13,63.87 35.02,63.87 34.97,63.82 34.97,63.77 34.92,63.72 34.81,63.72 34.76,63.77 34.76,63.82 34.7,63.87 33.27,63.87 32.34,62.94 32.34,61.35 32.12,61.13 31.8,61.13 31.62,60.95 U2601.9 U2601.2 30.25,60.95 30.07,61.13 29.28,61.13 29.03,60.88 29.03,60.29 C2604.1
MUX_XTAL_IN: length 6.4
  TOP w0.066: U3001.D1 34.57,52.74 34.19,52.74 33.39,53.54 R3007.2 32.56,53.54 C3021.1 32.19,53.49 31.94,53.75 29.87,53.75 29.05,52.93 Y3001.1
MUX_XTAL_OUT: length 4
  TOP w0.066: Y3001.3 31.6,54.08 C3022.1 32.54,54.05 R3007.1 33.17,54.05 34.08,53.14 34.57,53.14 U3001.C1
OSC_16M_IN: length 4.1
  BOTTOM w0.066: Y2501.1 10.39,17.41 10.39,18.89 C2522.1 10.62,19.21 10.62,19.79 R2509.2
OSC_16M_OUT: length 2.1
  BOTTOM w0.066: Y2501.3 10.06,18.84 C2523.1 10.06,19.81 R2511.2
OSC_32K_IN: length 4.7
  BOTTOM w0.066: R2514.1 14.07,19.15 C2528.1 R2512.2 15.67,18.54 16.36,17.85 Y2502.2
OSC_32K_OUT: length 2.8
  BOTTOM w0.066: Y2502.1 13.56,18.52 R2512.1 13.51,18.57 C2527.1 13.49,19.15 R2513.2
PACK_VSNS_M: length 7.8
  TOP w0.066: v2(46.28,16.84) 46.29,16.85 R604.1
  S3 w0.064: v2(46.28,16.84) 46.28,16.74 46.35,16.67 46.58,16.67 46.76,16.49 46.76,16.15 46.61,16 45.2,16 43.87,14.67 40.78,14.67 v2(40.68,14.58)
PHONE_ON_N: length 78.3
  TOP w0.066: JBTN1.1 47.15,58.17 47.52,57.8 D26009.2 47.54,57.17 C2605.1 48.05,56.88 v2(48.84,56.08) ; JBTN1.1 JBTN1.2 ; JBTN1.1 47.2,58.54 48.39,59.73 49.94,59.73 v6(50.11,59.9)
  S3 w0.064: v3(38.58,14.74) 38.19,15.13 v2(37.28,15.13) ; v2(48.84,56.08) 48.84,55.04 48.71,54.9 48.71,51.71 49.24,51.18 49.24,21.6 48.44,20.8 48.44,9.71 v3(47.47,8.74)
  S6 w0.064: v3(47.47,8.74) 46.86,9.35 43.54,9.35 43.01,9.87 41.97,9.87 40.82,11.02 40.82,11.98 38.58,14.22 v3(38.58,14.74)
  BOTTOM w0.066: TP2614.1 49.37,59.83 49.44,59.9 v6(50.11,59.9)
PM_AVDD_BYP: length 4.7
  S3 w0.064: v2(35.58,16.26) 35.48,16.36 35.24,16.36 34.89,16.01 34.6,16.01 33.54,14.95 33.04,14.95 32.77,14.68 32.76,14.68 32.74,14.66 32.1,14.66 31.8,14.96 31.8,14.95 v2(31.78,14.95)
PM_DVDD_BYP: length 5
  S3 w0.064: v2(35.86,15.98) 35.6,15.98 35.51,16.07 35.51,16.07 35.4,16.18 35.23,16.18 34.92,15.87 34.79,15.87 33.63,14.71 33.63,14.52 33.43,14.32 33.1,14.32 33.04,14.38 32.74,14.38 32.62,14.5 v2(31.85,14.5)
PM_REF_BYP: length 5.3
  TOP w0.066: C716.1 v2(31.64,13.51)
  S3 w0.06: 31.64,13.51 v2(31.64,13.51)
  S3 w0.064: v2(35.58,15.7) 35.48,15.6 34.95,15.6 34.63,15.28 34.63,15.13 33.57,14.07 33.57,13.67 33.27,13.37 32.85,13.37 32.84,13.36 32.03,13.36 31.88,13.51 31.64,13.51
PM_RESIN_N: length 93.8
  TOP w0.066: JCTL1.8 43.25,52.62 43.49,52.38 v2(43.49,50.82) ; v2(38.86,43.3) 39.36,43.3 D26008.2 39.36,43.09 39.49,42.96 v2(41.17,42.96) ; PMIC1.N9 v2(36.52,15.41)
  S3 w0.064: v3(38.84,42.34) 38.86,42.36 v2(38.86,43.3) ; v2(43.49,50.82) 43.49,50.64 42.34,49.49 42.34,46.02 42.72,45.64 42.72,44.18 41.5,42.96 v2(41.17,42.96) ; v2(36.52,15.41) v3(36.25,15.41)
  S6 w0.064: v3(36.25,15.41) 36.07,15.41 35.89,15.6 35.89,15.93 36.1,16.13 37.56,16.13 37.71,15.98 37.71,13.83 38.56,12.98 38.56,12.96 38.86,12.66 38.87,12.66 39.85,11.68 39.85,9.73 38.72,8.6 35.88,8.6 35.56,8.28 24.64,8.28 24.31,8.61 24.31,9.76 20.29,13.78 20.29,38.05 22.45,40.21 33.32,40.21 34.72,41.61 36.6,41.61 37.41,42.42 38.73,42.42 38.81,42.34 v3(38.84,42.34)
PM_XTAL_IN: length 4.9
  TOP w0.066: PMIC1.W5 35.3,13.72 35.3,13.29 35.09,13.08 34.91,13.08 34.01,12.18 34.01,10.73 34.16,10.58 C702.1 33.51,10.16 Y701.3
PM_XTAL_OUT: length 4.8
  TOP w0.066: PMIC1.Y4 34.9,13.43 33.45,11.99 32.14,11.99 31.98,11.83 C701.1 32.63,11.4 Y701.1
PMIC_FORCED_USB_BOOT: length 4
  S3 w0.064: v2(34.77,21.95) 35.05,21.67 35.61,21.67 35.66,21.62 35.66,19.18 v2(35.29,18.81)
PMIC_PWM_TP: length 5.6
  S3 w0.064: v2(36.14,17.96) 36.14,22.29 v2(35.26,23.17)
PON_OPTION: length 4.5
  TOP w0.066: PMIC1.R9 v2(36.58,14.85)
  S3 w0.06: v2(36.4,10.99) 36.4,11.03 ; 36.94,14.15 36.86,14.23 36.86,14.72 36.73,14.85 v2(36.58,14.85)
  S3 w0.064: 36.4,11.03 36.67,11.29 36.67,12.78 36.94,13.05 36.94,14.15
PS_HOLD: length 32.5
  TOP w0.066: R706.2 33.97,8.55 27.15,8.55 24.93,10.77 24.93,14.63 24.18,15.38 24.18,23.12 24.86,23.8 24.86,27.22 23.79,28.29 23.79,29.32 24.15,29.68 24.57,29.68 SOC1.AH27
PS_HOLD_R: length 7.1
  TOP w0.066: v2(35.89,9.96) 35.89,9.32 TP706.1 35.79,8.69 R709.1
  S3 w0.064: v2(36.73,15.14) 36.7,15.11 36.56,15.11 36.08,14.63 36.08,12.37 35.95,12.24 35.95,11.2 36.07,11.07 36.07,10.15 v2(35.89,9.96)
PWR_3P3V: length 192.8
  TOP w0.203: 13.67,6.58 C2610.1 13.67,6.87 v2(13.64,6.9) ; 13.67,6.58 R2613.1 ; 13.67,6.58 13.85,6.39 QWIIC1.2
  TOP w0.254: U3004.1 27.6,60.82 v2(27.58,60.83) 28.73,61.98 R2735.1
  S3 w0.203: v2(27.58,60.83) 27.58,64.96 v3(27.2,65.35) ; v2(47.45,3.25) v2(45.55,3.25) v2(43.64,3.25) 43.63,3.25 43.62,3.26 v2(41.73,3.26) 41.37,3.26 v3(41.27,3.35) ; v3(14.35,8.05) 13.78,8.05 13.47,7.74 13.47,7.07 v2(13.64,6.9) 14.25,6.29 15.74,6.29 v2(16.01,6.56)
  V4 w0.203: JANALOG1.4 3.59,33.02 ; JANALOG1.4 2.54,34.07 ; JANALOG1.4 2.54,31.97 ; JANALOG1.4 1.49,33.02 ; v3(14.35,8.05) 14.72,8.42 23.83,8.42 25.16,9.75 31.52,9.75 37.92,3.35 v3(41.27,3.35) ; 2.54,37.05 JANALOG1.2 ; JANALOG1.2 3.59,38.1 ; JANALOG1.2 1.49,38.1
  S6 w0.203: v5(13.16,27.76) 13.16,28.42 13.31,28.57 v5(13.31,29.57) ; v5(10.9,27.61) 10.72,27.43 v3(10.64,27.43) ; v5(8.08,38.96) v3(7.52,38.96) ; v3(11.4,20.17) 11.4,20.32 v5(11.53,20.45) ; 47.14,47.83 v5(47.24,47.73) ; v3(7.69,25.15) v5(7.69,24.82) 7.9,24.61 v5(8.9,24.61) ; v5(18.9,14.94) v3(18.9,15.34) ; v3(9.35,22.15) 9.35,22.2 9.12,22.42 v5(9.09,22.42) ; v5(8.9,27.11) 8.65,27.36 v3(7.98,27.36) v5(7.65,27.36) ; v5(7.72,21.92) v3(7.44,21.92) ; v4(32.38,11.86) v3(32.38,11.56) ; v5(18.96,32.92) 18.57,33.31 18.57,36.21 v5(18.97,36.61)
  S6 w1: 27.47,65.51 28.67,65.51 31.76,62.42 31.76,60.15 32.33,59.59 34.85,59.59 36.11,60.84 40.48,60.84 41.3,60.02 43.21,60.02 44.31,61.12 46.53,61.12 47.14,60.51 47.14,45.67 v5(47.29,45.52)
  G7 w0.203: JANALOG1.2 2.54,39.15 ; JANALOG1.2 2.54,37.05 ; JANALOG1.2 1.49,38.1 ; JANALOG1.2 3.59,38.1 ; v5(9.9,22.11) 9.4,22.11 v5(9.09,22.42) ; JANALOG1.4 2.54,34.07 ; JANALOG1.4 3.59,33.02 ; JANALOG1.4 1.49,33.02 ; v4(32.38,11.86) 32.38,12.93 32.59,13.14 v5(33.28,13.14) 34.92,13.14 v5(35.32,13.54) ; v5(14.4,21.61) 14.58,21.79 14.58,22.29 v5(14.9,22.61)
  G7 w1: v4(25.62,65.55) v4(25.39,65.55) 23.66,65.55 23.21,65.11 23.21,63.9 22.5,63.18 10.57,63.18 9.29,61.9 v5(9.29,60.83)
  BOTTOM w0.203: v5(18.96,32.92) 18.16,32.92 17.94,32.7 16.48,32.7 16.15,32.37 16.15,31.48 U1102.6 ; 16.79,27.23 16.43,26.87 C2509.1 15.62,26.87 15.36,26.61 MCU1.A11 ; 16.79,27.23 17.55,27.23 18.01,26.77 18.01,25.58 17.81,25.37 C2513.1 C2504.1 15.7,25.37 15.43,25.11 MCU1.A8 ; 16.79,27.23 16.79,28.92 15.98,29.73 ; MCU1.D13 13.25,27.76 v5(13.16,27.76) 13.05,27.76 MCU1.E13 ; U2501.5 44.71,45.43 44.48,45.66 ; U1101.11 17.91,37.32 C1102.1 18.78,36.8 v5(18.97,36.61) ; 44.48,45.66 C2529.1 45.46,45.89 R2643.1 46.91,45.9 v5(47.29,45.52) ; 44.48,45.66 44.06,45.23 U2501.4 ; v5(14.9,22.61) 15.01,22.61 16.36,21.26 C2503.1 C2505.1 17.88,21.26 18.41,20.73 18.41,15.42 v5(18.9,14.94) ; v5(47.24,47.73) 46.99,47.47 R2642.1 ; v5(11.53,20.45) C2506.1 11.9,20.46 MCU1.G1 ; v5(9.09,22.42) MCU1.N3 8.67,22.61 7.98,21.92 v5(7.72,21.92) C2518.1 ; C2616.1 6.81,38.25 ; R2666.1 v5(33.28,13.14) ; C2508.1 v5(7.69,24.82)
  BOTTOM w0.524: JANALOG1.4 1.02,34.54 1.02,36.58 JANALOG1.2
  vias: v3(9.04,61.28) v3(9.4,61.45) v3(9.43,61.09) v3(9.76,61.48) v3(9.81,61.12) v3(10.91,4.46) v3(11.11,4.13) v3(11.33,4.46) v3(11.53,4.12) v3(11.75,4.46) v3(11.98,4.13) v3(12.19,4.45) v3(12.88,30.02) v3(12.95,29.59) v3(13.33,20.55) v3(13.31,20.12) v3(26.42,65.73) v3(26.79,65.74) v3(26.81,65.36) v3(27.21,65.72) v4(8.76,61.22) v4(8.76,60.83) v4(8.88,61.01) v4(8.9,60.65) v4(9.03,60.84) v4(9.15,61.01) v4(9.16,60.65) v4(9.42,60.65) v4(9.56,60.83) v4(9.7,60.65) v4(10.63,4.97) v4(10.82,4.81) v4(10.96,4.98) v4(11.15,4.82) v4(11.31,4.98) v4(11.5,4.82) v4(11.65,4.98) v4(11.84,4.82) v4(11.99,4.98) v4(12.18,4.82) v4(13.23,30.05) v4(13.16,29.82) v4(13.41,29.79) v4(25.4,65.79) v4(25.39,65.32) v4(25.62,65.79) v4(25.62,65.32) v4(25.85,65.8) v4(25.85,65.56) v4(25.84,65.33) v4(26.08,65.8) v4(26.08,65.56) v4(26.07,65.33) v5(8.76,61.22) v5(8.76,60.83) v5(8.88,61.01) v5(8.9,60.65) v5(9.03,60.84) v5(9.15,61.01) v5(9.16,60.65) v5(9.42,60.65) v5(9.56,60.83) v5(9.7,60.65) v5(10.63,4.97) v5(10.82,4.81) v5(10.96,4.98) v5(11.15,4.82) v5(11.31,4.98) v5(11.5,4.82) v5(11.65,4.98) v5(11.84,4.82) v5(11.99,4.98) v5(12.18,4.82) v5(13.23,30.05) v5(13.16,29.82) v5(13.41,29.79)
PWR_3P8V: length 17.7
  S6 w0.203: v5(14.96,41.77) 14.79,41.61 v3(14.63,41.61) 11.22,41.61 v5(9.95,42.88) ; v3(15.29,42.32) 15.45,42.32 v5(15.56,42.43) ; v5(12.73,36.78) 13.01,36.78 v3(13.16,36.93)
  BOTTOM w0.203: v5(9.65,31.84) 9.91,31.58 10.79,31.58 11.01,31.8 R2804.1 11.81,32.95 11.81,34.67 12.19,35.05 U2802.4 12.73,35.3 C2806.1 v5(12.73,36.78) ; v5(14.96,41.77) 14.99,41.74 14.99,40.49 14,39.5 C2803.1 13.47,39.5 13.36,39.6
  vias: v3(12.77,37.55) v3(13.04,37.27) v4(9.64,32.1) v4(9.95,43.34) v4(9.95,43.12) v4(9.88,32.12) v4(9.88,31.84) v4(12.71,36.56) v4(12.87,36.97) v4(12.92,36.62) v5(9.64,32.1) v5(9.95,43.34) v5(9.95,43.12) v5(9.88,32.12) v5(9.88,31.84) v5(12.71,36.56) v5(12.87,36.97) v5(12.92,36.62)
QCA_SB_CLK: length 45.3
  TOP w0.066: v2(9.97,60.42) 7.88,60.42 6.7,61.6 3.98,61.6 3.53,61.15 R2902.1
  S3 w0.064: v2(9.97,60.42) 10.16,60.23 10.16,50.03 9.68,49.54 9.68,46.84 11.52,45 11.52,39.73 14.43,36.82 17.23,36.82 17.77,36.28 21.57,36.28 v2(24.97,32.88)
QCA_SB_CLK_R: length 12.8
  TOP w0.066: R2902.2 4.03,61.25 4.21,61.43 6.61,61.43 7.86,60.18 10.12,60.18 11.43,61.49 13.95,61.49 U2901.6
QCA_SB_DATA: length 39.6
  S3 w0.064: v2(24.97,33.28) 24.85,33.28 21.64,36.49 17.86,36.49 17.34,37.01 14.52,37.01 11.7,39.83 11.7,45.2 9.93,46.96 9.93,49.35 10.56,49.98 v2(10.56,62.5)
QREFS_CXO_REXT: length 1.8
  TOP w0.066: SOC1.T30 29.37,28.27 29.41,28.23 R1601.1
QUIET_THERM: length 1.2
  S3 w0.064: v2(39.6,14.63) 39.59,14.64 39.59,14.97 v3(39.42,15.14)
  S6 w0.064: v3(39.42,15.14) 39.42,14.58 v5(39.47,14.53)
RESOUT_N: length 13.3
  TOP w0.066: SOC1.AJ26 23.64,29.55 23.64,28.2 24.66,27.18 24.66,23.84 23.93,23.11 v2(23.93,21.55)
  S3 w0.064: v2(23.93,21.55) 25.2,21.55 26.1,22.45 v3(26.36,22.45)
  S6 w0.066: v5(27.22,22.8) 26.87,22.45 v3(26.36,22.45)
RFCLK1_TP: length 3.2
  TOP w0.066: PMIC1.W1 33.2,12.75 31.86,12.75 31.74,12.87 TP701.1
RFCLK2: length 5.5
  S3 w0.064: v2(34.45,14) 34.25,13.8 34.25,13.18 34.25,13.18 34.25,13.03 33.65,12.43 32.63,12.43 32.62,12.44 31.3,12.44 30.68,13.06 v2(30.3,13.06)
RFCLK3_TP: length 8.1
  S3 w0.064: v2(35.02,14.66) 34.95,14.66 34.83,14.54 34.83,12.87 33.92,11.97 30.85,11.97 30.71,12.12 29.62,12.12 29.34,11.84 v2(29.34,11.66)
RTC_SLEEP_CLK: length 69.2
  TOP w0.066: v2(4.99,49.16) 5.01,49.19 R2903.1 5.6,49.18 R1204.1
  S3 w0.064: v2(4.99,49.16) 4.9,49.08 4.9,16.06 7.89,13.07 18.87,13.07 21.79,15.99 29.3,15.99 30.77,17.46 36.65,17.46 v2(36.71,17.39)
RTC_SLEEP_CLK_R: length 18.4
  TOP w0.066: U2901.9 10.98,61.82 7.92,61.82 v2(7.75,61.65) ; R2903.2 6.95,49.69 v2(8.09,50.83)
  S3 w0.064: v2(7.75,61.65) 7.75,59.89 8.16,59.48 8.16,57.91 7.9,57.65 7.9,56.29 8.09,56.1 v2(8.09,50.83)
SBU1_AUXP: length 5.5
  TOP w0.051: v2(35.83,57.23) 35.7,57.36 35.7,57.5
  S3 w0.048: v2(34.93,53.54) 34.98,53.6 34.98,53.78 34.68,54.08 34.68,54.98 34.44,55.23 34.44,56.43 34.78,56.77 35.82,56.77 35.91,56.87 35.91,57.14 v2(35.83,57.23)
SBU2_AUXN: length 6
  TOP w0.051: 36.24,57.5 36.24,57.31 v2(36.16,57.23)
  S3 w0.048: v2(36.16,57.23) 36.07,57.14 36.07,56.8 35.88,56.62 34.84,56.62 34.59,56.37 34.59,55.29 34.84,55.05 34.84,54.15 35.14,53.84 35.14,53.35 v2(34.93,53.14)
SD_CARD_DET_N_TP: length 2.2
  TOP w0.066: TP1315.1 22.85,36.56 23.01,36.72 24.34,36.72 24.57,36.49 SOC1.AH10
SDC1_CLK: length 19
  TOP w0.066: R1207.2 v2(36.25,26.55)
  S3 w0.079: v2(36.25,26.55) 36.4,26.4 36.4,24.75 32.93,21.28 32.93,20.84 32.85,20.75 32.69,20.75 32.62,20.83 32.62,21.44 32.54,21.52 32.38,21.52 32.3,21.44 32.3,20.81 32.23,20.74 32.07,20.74 31.99,20.82 31.99,21.44 31.91,21.52 31.75,21.52 31.67,21.44 31.67,20.81 31.6,20.74 31.44,20.74 31.36,20.82 31.36,21.44 31.28,21.52 31.12,21.52 31.04,21.44 31.04,20.81 30.97,20.74 30.81,20.74 30.73,20.82 30.73,21.44 30.65,21.52 29.57,21.52 29.25,21.2 28.55,21.2 v3(28.2,20.85)
  S6 w0.064: v5(28.22,22.3) 28.2,22.28 v3(28.2,20.85)
SDC1_CLK_TR: length 2.6
  TOP w0.066: R1207.1 35.35,26.55 35.35,27.15 35.7,27.5 35.7,28.55 35.37,28.88 SOC1.A29
SDC1_CMD: length 22
  S3 w0.064: 33.86,29.23 34.09,29.46 34.44,29.46 34.57,29.59 v2(34.57,29.68)
  S3 w0.079: 33.86,29.23 33.86,27.94 34.05,27.75 v3(34.05,25.6)
  S6 w0.079: v5(34.1,25.3) 34.1,25.6 v3(34.05,25.6)
  BOTTOM w0.084: EMMC1.M5 28.47,22.56 30.11,22.56 30.24,22.69 30.24,25.17 30.37,25.3 30.53,25.3 30.62,25.21 30.62,24.22 30.7,24.14 30.87,24.14 30.95,24.22 30.95,25.21 31.04,25.3 31.2,25.3 31.29,25.21 31.29,24.22 31.37,24.14 31.54,24.14 31.62,24.22 31.62,25.21 31.71,25.3 31.87,25.3 31.96,25.21 31.96,24.22 32.04,24.14 32.21,24.14 32.29,24.22 32.29,25.21 32.38,25.3 32.54,25.3 32.63,25.21 32.63,24.22 32.71,24.14 32.88,24.14 32.96,24.22 32.96,25.21 33.05,25.3 R2114.2
SDC1_DATA_0: length 22.5
  S3 w0.064: v2(34.97,29.28) 35.15,29.1 35.15,28.8 35.43,28.52 35.44,28.52
  S3 w0.079: 35.44,28.52 35.75,28.21 35.75,24.68 32.77,21.7 29.45,21.7 29.15,21.4 28.2,21.4 27.53,20.73 v3(26.83,20.73)
  S6 w0.079: v3(26.83,20.73) 26.59,20.49 24.16,20.49 22.4,22.25 22.4,23.39 v5(22.82,23.82)
SDC1_DATA_1: length 21.2
  S3 w0.079: v3(26.42,21.05) 27.5,21.05 28.05,21.6 29.05,21.6 29.34,21.89 32.68,21.89 35.55,24.75 35.55,28.17 34.97,28.75 v2(34.97,28.88)
  S6 w0.079: v5(22.82,23.31) 22.6,23.09 22.6,22.4 24.33,20.67 24.55,20.67 24.63,20.75 24.63,20.79 24.71,20.87 24.87,20.87 24.95,20.79 24.95,20.75 25.02,20.67 25.18,20.67 25.26,20.75 25.26,20.79 25.34,20.87 25.5,20.87 25.58,20.79 25.58,20.75 25.65,20.67 26.03,20.67 v3(26.42,21.05)
SDC1_DATA_2: length 20.9
  S3 w0.079: v2(34.97,28.48) 34.97,28.38 35.35,28 35.35,24.85 32.55,22.05 29.25,22.05 29,21.8 27.96,21.8 27.53,21.37 26.05,21.37 25.93,21.25 v3(25.93,21.07)
  S6 w0.079: v5(22.82,22.8) 22.82,22.53 23.41,21.94 23.52,21.94 23.7,22.12 23.81,22.12 23.92,22.01 23.92,21.9 23.74,21.72 23.74,21.61 23.85,21.5 23.96,21.5 24.14,21.68 24.25,21.68 24.36,21.57 24.36,21.46 24.18,21.28 24.18,21.17 24.28,21.07 24.42,21.07 24.49,21.15 24.49,21.27 24.57,21.35 24.73,21.35 24.81,21.27 24.81,21.15 24.89,21.07 25.04,21.07 25.12,21.15 25.12,21.27 25.2,21.35 25.36,21.35 25.44,21.27 25.44,21.15 25.52,21.07 v3(25.93,21.07)
SDC1_DATA_3: length 21.8
  S3 w0.064: v2(34.57,29.28) 34.76,29.09
  S3 w0.079: v3(27.44,21.72) 27.72,22 28.9,22 29.12,22.23 29.42,22.23 29.5,22.3 29.5,22.42 29.58,22.5 29.74,22.5 29.81,22.42 29.81,22.3 29.89,22.23 30.05,22.23 30.13,22.3 30.13,22.42 30.21,22.5 30.36,22.5 30.44,22.42 30.44,22.3 30.52,22.23 32.43,22.23 35.15,24.95 35.15,27.95 34.76,28.34 34.76,29.09
  S6 w0.079: v5(23.22,24.3) 23.54,23.98 24.01,23.98 24.91,24.88 26.69,24.88 27.44,24.13 v3(27.44,21.72)
SDC1_DATA_4: length 21.7
  S3 w0.079: v3(26.54,21.7) 27.24,22.4 28.8,22.4 29.55,23.15 29.85,23.15 29.93,23.07 29.93,22.95 30.01,22.87 30.17,22.87 30.24,22.95 30.24,23.07 30.32,23.15 32.85,23.15 34.75,25.05 34.75,27.85 34.36,28.24 34.36,28.67 v2(34.57,28.88)
  S6 w0.079: v5(23.22,23.8) 23.47,23.55 24.08,23.55 24.98,24.45 26.62,24.45 26.94,24.12 26.94,23.27 26.72,23.05 26.37,23.05 26.03,22.71 26.03,22.12 26.45,21.7 v3(26.54,21.7)
SDC1_DATA_5: length 22.3
  S3 w0.064: v2(34.57,28.48) 34.57,28.29
  S3 w0.079: v3(26.99,21.72) 27.47,22.2 28.85,22.2 29.31,22.66 30.67,22.66 30.75,22.74 30.75,22.88 30.83,22.95 30.99,22.95 31.07,22.88 31.07,22.74 31.15,22.66 31.3,22.66 31.38,22.74 31.38,22.88 31.46,22.95 31.62,22.95 31.7,22.88 31.7,22.74 31.78,22.66 31.93,22.66 32.01,22.74 32.01,22.88 32.09,22.95 32.25,22.95 32.33,22.88 32.33,22.74 32.4,22.66 32.61,22.66 34.95,25 34.95,27.91 34.57,28.29
  S6 w0.079: v3(26.99,21.72) 26.64,21.37 26.43,21.37 25.81,21.99 25.81,22.82 26.31,23.32 26.6,23.32 26.72,23.44 26.72,24.03 26.51,24.24 25.11,24.24 24.17,23.3 v5(23.22,23.3)
SDC1_DATA_6: length 21.3
  S3 w0.064: v2(34.17,29.28) 33.99,29.1 33.99,28.96 33.98,28.96 33.98,28.81 33.99,28.81 33.99,28.68 34.03,28.63
  S3 w0.079: v3(25.15,22.15) 25.8,22.8 28.65,22.8 29.4,23.55 32.7,23.55 34.35,25.2 34.35,27.7 34.03,28.02 34.03,28.63
  S6 w0.079: v5(23.22,22.8) 23.28,22.86 24.12,22.86 25.26,24 26.44,24 26.51,23.93 26.51,23.62 26.44,23.55 25.84,23.55 25.75,23.46 25.75,23.28 25.15,22.68 v3(25.15,22.15)
SDC1_DATA_7: length 21
  S3 w0.064: 34.38,24.97 34.39,24.97
  S3 w0.079: 34.38,24.97 32.77,23.35 29.5,23.35 28.75,22.6 26.9,22.6 25.85,21.55 v3(25.7,21.55) ; v2(34.17,28.88) 34.2,28.85 34.2,28.12 34.55,27.77 34.55,25.13 34.39,24.97
  S6 w0.079: v5(23.32,22.38) 23.32,22.53 23.4,22.61 23.63,22.61 23.84,22.4 23.95,22.4 25.17,23.62 25.28,23.62 25.39,23.51 25.39,23.39 24.18,22.18 24.18,22.07 24.53,21.71 25.54,21.71 v3(25.7,21.55)
  BOTTOM w0.084: v5(23.32,22.38) 23.24,22.3 EMMC1.B6
SDC1_RCLK: length 20.6
  S3 w0.079: v2(35.37,29.28) 35.56,29.09 35.56,28.69 36,28.25 36,24.9 v3(36.1,24.9)
  S6 w0.064: v5(34.5,24.75) 34.5,24.75 35.85,24.75
  S6 w0.079: v3(36.1,24.9) 36,24.9 35.85,24.75
  BOTTOM w0.084: EMMC1.H5 26.52,23.1 27.4,23.1 27.7,22.8 27.7,22.2 27.85,22.05 30.22,22.05 30.61,22.44 30.73,22.44 31.08,22.1 31.2,22.1 31.31,22.22 31.31,22.33 30.97,22.68 30.97,22.8 31.09,22.92 31.2,22.92 31.55,22.57 31.67,22.57 31.79,22.69 31.79,22.81 31.44,23.16 31.44,23.27 31.69,23.53 32.33,23.53 32.43,23.43 32.43,22.88 32.51,22.79 32.68,22.79 32.76,22.88 32.76,23.42 32.87,23.53 33.1,23.53 33.47,23.89 33.47,24.61 33.61,24.75 R2113.1 34.5,24.75 v5(34.5,24.75)
SLEEP_CLK: length 31.8
  TOP w0.066: v2(9.19,49) 9.01,49.18 R1204.2
  G2 w0.066: v1(24.57,30.08) 24.57,30.36 24.41,30.52 23.97,30.52 v2(23.76,30.73)
  S3 w0.064: v2(9.19,49) 9.19,46.6 11.13,44.66 11.13,39.47 12.22,38.38 12.22,36.1 14.15,34.18 19.27,34.18 22.72,30.73 v2(23.76,30.73)
SM_LNBBCLK1: length 19.4
  TOP w0.05: 28.97,28.33 28.97,28.88 SOC1.U29
  TOP w0.066: R702.1 29.7,13.66 27.27,13.66 26.18,14.75 26.18,21.86 28.96,24.64 28.96,28.33 28.97,28.33
